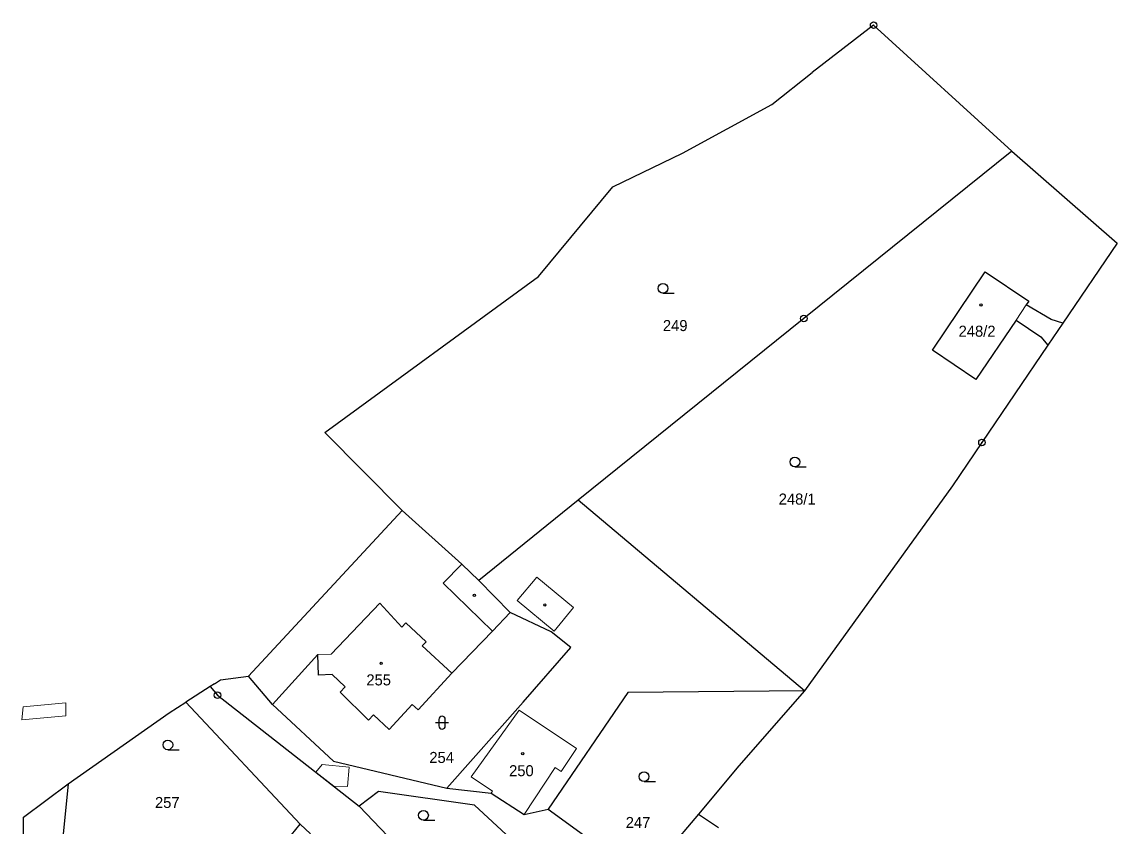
# Model space of a CAD drawing. Extents: x -727701 to -724405, y -960481 to -957284.
# Drawn here: x -727034.5 to -726865.8, y -957960.6 to -957836.7 of the extents above; entities that cross this region are included whole.
import ezdxf
from ezdxf.enums import TextEntityAlignment as Align

# ---------------------------------------------------------------- set-up
doc = ezdxf.new("R2010")
doc.units = 0
doc.header["$LTSCALE"] = 0.68
for name, color, linetype, lineweight in [('1', 7, 'Continuous', 25), ('13', 7, 'Continuous', 13), ('3', 7, 'Continuous', 25), ('4', 7, 'Continuous', 13), ('5', 7, 'Continuous', 25), ('8', 7, 'Continuous', 25)]:
    doc.layers.add(name, color=color, linetype=linetype, lineweight=lineweight)
doc.layers.add('2', color=7, linetype='Continuous')

msp = doc.modelspace()

# ---------------------------------------------------------------- linework, layer by layer
at = {"layer": '1'}
for p, q in [((-726903.28, -957837.23), (-726912.74, -957844.55)), ((-726903.28, -957837.23), (-726882.01, -957856.64)), ((-726918.94, -957849.45), (-726912.74, -957844.55)), ((-726932.7, -957856.94), (-726918.94, -957849.45)), ((-726882.01, -957856.64), (-726914.03, -957882.42)), ((-726882.01, -957856.64), (-726865.78, -957870.8)), ((-726943.45, -957862.12), (-726932.7, -957856.94)), ((-726954.88, -957875.94), (-726943.45, -957862.12)), ((-726865.78, -957870.8), (-726874.16, -957883.17)), ((-726894.21, -957887.28), (-726886.08, -957875.22)), ((-726886.08, -957875.22), (-726879.39, -957879.77)), ((-726987.8, -957899.97), (-726954.88, -957875.94)), ((-726879.39, -957879.77), (-726879.77, -957880.34)), ((-726875.91, -957882.59), (-726879.77, -957880.34)), ((-726914.03, -957882.42), (-726948.8, -957910.4)), ((-726881.35, -957882.68), (-726887.52, -957891.84)), ((-726881.35, -957882.68), (-726877.53, -957885.24)), ((-726874.16, -957883.17), (-726876.45, -957886.55)), ((-726874.16, -957883.17), (-726875.91, -957882.59)), ((-726877.53, -957885.24), (-726876.45, -957886.55)), ((-726876.45, -957886.55), (-726886.6, -957901.53)), ((-726887.52, -957891.84), (-726894.21, -957887.28)), ((-726975.93, -957912.02), (-726987.8, -957899.97)), ((-726886.6, -957901.53), (-726891.14, -957908.23)), ((-726891.14, -957908.23), (-726913.92, -957939.81)), ((-726948.8, -957910.4), (-726964.11, -957922.78)), ((-726913.92, -957939.81), (-726948.8, -957910.4)), ((-726999.59, -957937.52), (-726975.93, -957912.02)), ((-726966.71, -957920.28), (-726975.93, -957912.02)), ((-726966.71, -957920.28), (-726964.11, -957922.78)), ((-726964.11, -957922.78), (-726959.25, -957927.7)), ((-726959.25, -957927.7), (-726962.01, -957930.59)), ((-726952.94, -957930.68), (-726959.25, -957927.7)), ((-726962.01, -957930.59), (-726968.26, -957937.09)), ((-726949.95, -957933.14), (-726952.94, -957930.68)), ((-726988.89, -957934.18), (-726995.87, -957941.91)), ((-726988.8, -957937.36), (-726988.89, -957934.18)), ((-726957.27, -957941.52), (-726949.95, -957933.14)), ((-727003.89, -957938.11), (-726999.59, -957937.52)), ((-726995.87, -957941.91), (-726999.59, -957937.52)), ((-726986.69, -957937.3), (-726988.8, -957937.36)), ((-726984.69, -957939.19), (-726986.69, -957937.3)), ((-726968.26, -957937.09), (-726973.46, -957942.74)), ((-727005.46, -957939.12), (-727009.22, -957941.55)), ((-727004.82, -957938.71), (-727005.46, -957939.12)), ((-727005.46, -957939.12), (-727004.34, -957940.46)), ((-727004.82, -957938.71), (-727003.89, -957938.11)), ((-726985.48, -957939.99), (-726984.69, -957939.19)), ((-727004.34, -957940.46), (-726982.51, -957957.55)), ((-726981.09, -957944.29), (-726985.48, -957939.99)), ((-726941.12, -957940.04), (-726953.44, -957958.01)), ((-726913.92, -957939.81), (-726941.12, -957940.04)), ((-727011.78, -957943.2), (-727009.22, -957941.55)), ((-726991.64, -957960.34), (-727009.22, -957941.55)), ((-726995.87, -957941.91), (-726986.5, -957950.61)), ((-726974.37, -957941.9), (-726977.93, -957945.76)), ((-726973.46, -957942.74), (-726974.37, -957941.9)), ((-726969, -957954.77), (-726957.27, -957941.52)), ((-727027.33, -957954.13), (-727011.78, -957943.2)), ((-726980.31, -957943.49), (-726981.09, -957944.29)), ((-726977.93, -957945.76), (-726980.31, -957943.49)), ((-726986.5, -957950.61), (-726969, -957954.77)), ((-727034.25, -957959.25), (-727027.33, -957954.13)), ((-727027.33, -957954.13), (-727028.21, -957962.91)), ((-726979.54, -957955.3), (-726982.51, -957957.55)), ((-726964.74, -957957.39), (-726979.54, -957955.3)), ((-726969, -957954.77), (-726962.2, -957955.55)), ((-726962.2, -957955.55), (-726957.09, -957958.85)), ((-726982.51, -957957.55), (-726969.33, -957971.38)), ((-726959.21, -957962.52), (-726964.74, -957957.39)), ((-727034.33, -957975.58), (-727034.25, -957959.25)), ((-726957.09, -957958.85), (-726953.44, -957958.01)), ((-726953.44, -957958.01), (-726938.67, -957968.71)), ((-726930.24, -957958.81), (-726938.67, -957968.71)), ((-726930.24, -957958.81), (-726927.19, -957960.86)), ((-727006.95, -957979.03), (-726991.64, -957960.34)), ((-726990.05, -957961.81), (-726991.64, -957960.34))]:
    msp.add_line(p, q, dxfattribs=at)
msp.add_lwpolyline([(-726913.92, -957939.81), (-726924.04, -957951.34), (-726930.24, -957958.81)], dxfattribs=at)
at = {"layer": '13'}
for points in [[(-727027.7, -957941.65), (-727034.3, -957942.25), (-727034.48, -957944.28), (-727027.69, -957943.65)], [(-726984.06, -957951.55), (-726988.24, -957951.15), (-726989.19, -957952.32), (-726986.42, -957954.49), (-726984.35, -957954.54)]]:
    msp.add_lwpolyline(points, close=True, dxfattribs=at)
at = {"layer": '3'}
for p, q in [((-726935.733, -957878.54), (-726933.983, -957878.54)), ((-726915.413, -957905.28), (-726913.663, -957905.28)), ((-726970.261, -957944.191), (-726970.261, -957945.192)), ((-726969.259, -957945.192), (-726969.259, -957944.191)), ((-726970.761, -957944.691), (-726968.759, -957944.691)), ((-727011.993, -957948.87), (-727010.243, -957948.87)), ((-726938.653, -957953.76), (-726936.903, -957953.76)), ((-726972.623, -957959.72), (-726970.873, -957959.72))]:
    msp.add_line(p, q, dxfattribs=at)
for centre in [(-726935.7329, -957877.7898), (-726915.4129, -957904.5298), (-727011.9929, -957948.1198), (-726938.6529, -957953.0098), (-726972.6229, -957958.9698)]:
    msp.add_circle(centre, 0.75, dxfattribs=at)
for centre, start, end in [((-726969.76, -957944.1909), 0, 180), ((-726969.76, -957945.1909), 180, 359.98789)]:
    msp.add_arc(centre, 0.5, start, end, dxfattribs=at)
at = {"layer": '4'}
for p, q in [((-726879.77, -957880.34), (-726881.35, -957882.68)), ((-726966.71, -957920.28), (-726969.58, -957923.21)), ((-726958.2, -957925.87), (-726955.18, -957922.29)), ((-726955.18, -957922.29), (-726949.49, -957926.97)), ((-726962.01, -957930.59), (-726969.58, -957923.21)), ((-726979.32, -957926.27), (-726986.83, -957934.13)), ((-726979.32, -957926.27), (-726975.96, -957929.99)), ((-726952.49, -957930.58), (-726958.2, -957925.87)), ((-726949.49, -957926.97), (-726952.49, -957930.58)), ((-726975.96, -957929.99), (-726975.36, -957929.33)), ((-726975.36, -957929.33), (-726972.23, -957932.22)), ((-726972.23, -957932.22), (-726972.83, -957932.87)), ((-726988.89, -957934.18), (-726986.83, -957934.13)), ((-726972.83, -957932.87), (-726968.26, -957937.09)), ((-726965.27, -957953.02), (-726957.87, -957942.76)), ((-726957.87, -957942.76), (-726949.04, -957948.66)), ((-726949.04, -957948.66), (-726951.41, -957952.22)), ((-726952.32, -957951.58), (-726957.09, -957958.85)), ((-726951.41, -957952.22), (-726952.32, -957951.58)), ((-726962, -957955.24), (-726965.27, -957953.02)), ((-726962.2, -957955.55), (-726962, -957955.24))]:
    msp.add_line(p, q, dxfattribs=at)
at = {"layer": '5'}
for centre in [(-726886.7468, -957880.3392), (-726964.7768, -957925.0892), (-726953.9268, -957926.5492), (-726979.1368, -957935.5392), (-726957.3268, -957949.4692)]:
    msp.add_circle(centre, 0.175, dxfattribs=at)
at = {"layer": '8'}
for centre, radius in [((-726903.28, -957837.2299), 0.5), ((-726903.28, -957837.2299), 0.0303), ((-726914.03, -957882.4199), 0.5), ((-726914.03, -957882.4199), 0.0303), ((-726886.6, -957901.5299), 0.5), ((-726886.6, -957901.5299), 0.0303), ((-727004.34, -957940.4599), 0.5), ((-727004.34, -957940.4599), 0.0303)]:
    msp.add_circle(centre, radius, dxfattribs=at)

# ---------------------------------------------------------------- texts
at = {"layer": '2'}
for s, p in [('249', (-726935.74, -957884.365)), ('255', (-726981.42, -957938.955)), ('254', (-726971.72, -957950.905)), ('257', (-727013.98, -957957.845)), ('247', (-726941.47, -957960.925))]:
    msp.add_text(s, height=1.7, dxfattribs=at).set_placement(p)
for s, p in [('248/2', (-726887.35, -957885.235)), ('248/1', (-726915.06, -957911.095)), ('250', (-726957.539, -957952.945))]:
    msp.add_text(s, height=1.7, dxfattribs=at).set_placement(p, align=Align.CENTER)

doc.saveas('drawing.dxf')
